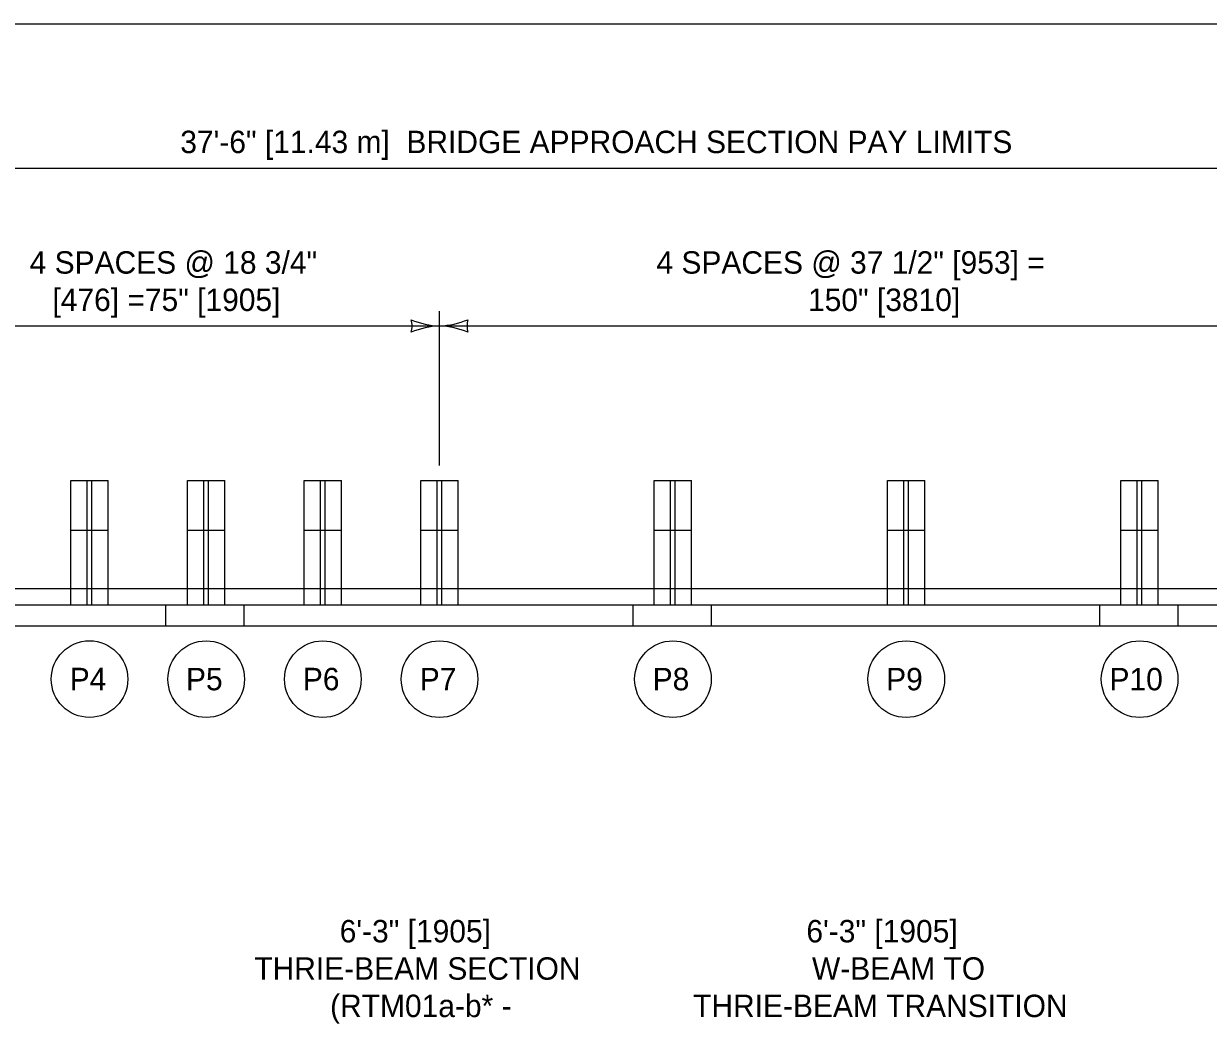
# Model space of a CAD drawing. Extents: x 49991 to 50160, y 49948 to 50051.
# Drawn here: x 50002.708 to 50005.881, y 49996.312 to 49998.999 of the extents above; entities that cross this region are included whole.
import ezdxf

# ---------------------------------------------------------------- set-up
doc = ezdxf.new("R2010")
doc.units = 0
for name, color, linetype in [('Level 1', 7, 'Continuous'), ('Level 2', 7, 'Continuous'), ('Level 3', 7, 'Continuous'), ('Level 4', 7, 'Continuous')]:
    doc.layers.add(name, color=color, linetype=linetype)

msp = doc.modelspace()

# ---------------------------------------------------------------- linework, layer by layer
at = {"layer": 'Level 1'}
for p, q in [((50002.8341, 49997.6431), (50002.8341, 49997.7764)), ((50002.8341, 49997.7764), (50002.9341, 49997.7764)), ((50002.9341, 49997.6431), (50002.9341, 49997.7764)), ((50003.1466, 49997.6431), (50003.1466, 49997.7764)), ((50003.1466, 49997.7764), (50003.2466, 49997.7764)), ((50003.2466, 49997.6431), (50003.2466, 49997.7764)), ((50003.4591, 49997.6431), (50003.4591, 49997.7764)), ((50003.4591, 49997.7764), (50003.5591, 49997.7764)), ((50003.5591, 49997.6431), (50003.5591, 49997.7764)), ((50003.7716, 49997.6431), (50003.7716, 49997.7764)), ((50003.7716, 49997.7764), (50003.8716, 49997.7764)), ((50003.8716, 49997.6431), (50003.8716, 49997.7764)), ((50004.3966, 49997.643), (50004.3966, 49997.7764)), ((50004.3966, 49997.7764), (50004.4966, 49997.7764)), ((50004.4966, 49997.643), (50004.4966, 49997.7764)), ((50005.0216, 49997.643), (50005.0216, 49997.7764)), ((50005.0216, 49997.7764), (50005.1216, 49997.7763)), ((50005.1216, 49997.643), (50005.1216, 49997.7763)), ((50005.6466, 49997.643), (50005.6466, 49997.7763)), ((50005.6466, 49997.7763), (50005.7466, 49997.7763)), ((50005.7466, 49997.643), (50005.7466, 49997.7763)), ((50002.8341, 49997.4431), (50002.8341, 49997.6431)), ((50002.8341, 49997.6431), (50002.9341, 49997.6431)), ((50002.8341, 49997.6431), (50002.9341, 49997.6431)), ((50002.9341, 49997.4431), (50002.9341, 49997.6431)), ((50003.1466, 49997.4431), (50003.1466, 49997.6431)), ((50003.1466, 49997.6431), (50003.2466, 49997.6431)), ((50003.1466, 49997.6431), (50003.2466, 49997.6431)), ((50003.2466, 49997.4431), (50003.2466, 49997.6431)), ((50003.4591, 49997.4431), (50003.4591, 49997.6431)), ((50003.4591, 49997.6431), (50003.5591, 49997.6431)), ((50003.4591, 49997.6431), (50003.5591, 49997.6431)), ((50003.5591, 49997.4431), (50003.5591, 49997.6431)), ((50003.7716, 49997.4431), (50003.7716, 49997.6431)), ((50003.7716, 49997.6431), (50003.8716, 49997.6431)), ((50003.7716, 49997.6431), (50003.8716, 49997.6431)), ((50003.8716, 49997.4431), (50003.8716, 49997.6431)), ((50004.3966, 49997.443), (50004.3966, 49997.643)), ((50004.3966, 49997.643), (50004.4966, 49997.643)), ((50004.3966, 49997.643), (50004.4966, 49997.643)), ((50004.4966, 49997.443), (50004.4966, 49997.643)), ((50005.0216, 49997.443), (50005.0216, 49997.643)), ((50005.0216, 49997.643), (50005.1216, 49997.643)), ((50005.0216, 49997.643), (50005.1216, 49997.643)), ((50005.1216, 49997.443), (50005.1216, 49997.643)), ((50005.6466, 49997.443), (50005.6466, 49997.643)), ((50005.6466, 49997.643), (50005.7466, 49997.643)), ((50005.6466, 49997.643), (50005.7466, 49997.643)), ((50005.7466, 49997.443), (50005.7466, 49997.643)), ((50002.6216, 49997.4869), (50002.8341, 49997.4869)), ((50002.9341, 49997.4869), (50003.1466, 49997.4869)), ((50003.2466, 49997.4869), (50003.4591, 49997.4869)), ((50003.5591, 49997.4869), (50003.7716, 49997.4869)), ((50003.8716, 49997.4869), (50004.3966, 49997.4869)), ((50004.4966, 49997.4869), (50005.0216, 49997.4869)), ((50005.1216, 49997.4869), (50005.6466, 49997.4869)), ((50005.7466, 49997.4869), (50006.2716, 49997.4869)), ((49999.8072, 49997.4432), (50011.6716, 49997.4427)), ((50002.8341, 49997.4431), (50002.9341, 49997.4431)), ((50003.0886, 49997.3869), (50003.0886, 49997.4431)), ((50003.1466, 49997.4431), (50003.2466, 49997.4431)), ((50003.4591, 49997.4431), (50003.5591, 49997.4431)), ((50003.7716, 49997.4431), (50003.8716, 49997.4431)), ((50004.3397, 49997.3868), (50004.3397, 49997.443)), ((50004.3966, 49997.443), (50004.4966, 49997.443)), ((50005.0216, 49997.443), (50005.1216, 49997.443)), ((50005.5897, 49997.3868), (50005.5897, 49997.443)), ((50005.6466, 49997.443), (50005.7466, 49997.443)), ((49999.8072, 49997.387), (50011.6716, 49997.3865))]:
    msp.add_line(p, q, dxfattribs=at)
msp.add_lwpolyline([(49999.3835, 49998.9992), (50016.7501, 49998.9992), (50016.7501, 49987.7988), (49999.3835, 49987.7988)], close=True, dxfattribs=at)
at = {"layer": 'Level 2'}
for centre in [(50002.8841, 49997.2443), (50003.1966, 49997.2442), (50003.509, 49997.2442), (50003.8215, 49997.2442), (50004.4466, 49997.2442), (50005.0715, 49997.2441), (50005.6966, 49997.2441)]:
    msp.add_circle(centre, 0.1026, dxfattribs=at)
at = {"layer": 'Level 3'}
for p, q in [((50000.679, 49998.6127), (50008.1966, 49998.6127)), ((50003.8216, 49997.8164), (50003.8216, 49998.2299)), ((50002.5716, 49998.1899), (50003.8216, 49998.1899)), ((50003.8216, 49998.1899), (50006.3216, 49998.1899))]:
    msp.add_line(p, q, dxfattribs=at)
for centre, radius, start, end in [((50003.8308, 49998.412), 0.2223, 247.456, 267.6395), ((50003.6934, 49998.1899), 0.0548, 342.1388, 17.8612), ((50003.8331, 49997.9572), 0.233, 92.8273, 112.0772), ((50003.8102, 49998.4226), 0.233, 272.8273, 292.0772), ((50003.8125, 49997.9678), 0.2223, 67.456, 87.6395), ((50003.9499, 49998.1899), 0.0548, 162.1388, 197.8612)]:
    msp.add_arc(centre, radius, start, end, dxfattribs=at)
at = {"layer": 'Level 4'}
for p, q in [((50002.8779, 49997.6431), (50002.8779, 49997.7764)), ((50002.8904, 49997.6431), (50002.8904, 49997.7764)), ((50003.1904, 49997.6431), (50003.1904, 49997.7764)), ((50003.2029, 49997.6431), (50003.2029, 49997.7764)), ((50003.5029, 49997.6431), (50003.5029, 49997.7764)), ((50003.5154, 49997.6431), (50003.5154, 49997.7764)), ((50003.8154, 49997.6431), (50003.8154, 49997.7764)), ((50003.8279, 49997.6431), (50003.8279, 49997.7764)), ((50004.4404, 49997.643), (50004.4404, 49997.7764)), ((50004.4529, 49997.643), (50004.4529, 49997.7764)), ((50005.0654, 49997.643), (50005.0654, 49997.7763)), ((50005.0779, 49997.643), (50005.0779, 49997.7763)), ((50005.6904, 49997.643), (50005.6904, 49997.7763)), ((50005.7029, 49997.643), (50005.7029, 49997.7763)), ((50002.8779, 49997.4431), (50002.8779, 49997.6431)), ((50002.8904, 49997.4431), (50002.8904, 49997.6431)), ((50003.1904, 49997.4431), (50003.1904, 49997.6431)), ((50003.2029, 49997.4431), (50003.2029, 49997.6431)), ((50003.5029, 49997.4431), (50003.5029, 49997.6431)), ((50003.5154, 49997.4431), (50003.5154, 49997.6431)), ((50003.8154, 49997.4431), (50003.8154, 49997.6431)), ((50003.8279, 49997.4431), (50003.8279, 49997.6431)), ((50004.4404, 49997.443), (50004.4404, 49997.643)), ((50004.4529, 49997.443), (50004.4529, 49997.643)), ((50005.0654, 49997.443), (50005.0654, 49997.643)), ((50005.0779, 49997.443), (50005.0779, 49997.643)), ((50005.6904, 49997.443), (50005.6904, 49997.643)), ((50005.7029, 49997.443), (50005.7029, 49997.643)), ((50002.8341, 49997.4869), (50002.9341, 49997.4869)), ((50003.1466, 49997.4869), (50003.2466, 49997.4869)), ((50003.4591, 49997.4869), (50003.5591, 49997.4869)), ((50003.7716, 49997.4869), (50003.8716, 49997.4869)), ((50004.3966, 49997.4869), (50004.4966, 49997.4869)), ((50005.0216, 49997.4869), (50005.1216, 49997.4869)), ((50005.6466, 49997.4869), (50005.7466, 49997.4869)), ((50003.2985, 49997.3868), (50003.2985, 49997.4431)), ((50004.5497, 49997.3868), (50004.5497, 49997.443)), ((50005.7997, 49997.3868), (50005.7997, 49997.443))]:
    msp.add_line(p, q, dxfattribs=at)

# ---------------------------------------------------------------- texts
at = {"layer": 'Level 2'}
for s, p in [('37\'-6" [11.43 m]  BRIDGE APPROACH SECTION PAY LIMITS', (50003.1271, 49998.6527)), ('4 SPACES @ 18 3/4"', (50002.7237, 49998.3299)), ('4 SPACES @ 37 1/2" [953] =', (50004.4025, 49998.3299)), (' [476] =75" [1905]', (50002.7624, 49998.2299)), ('150" [3810]', (50004.8084, 49998.2299)), ('P4', (50002.831, 49997.2145)), ('P5', (50003.1424, 49997.2144)), ('P6', (50003.4554, 49997.2145)), ('P7', (50003.7685, 49997.2144)), ('P8', (50004.3924, 49997.2144)), ('P9', (50005.0177, 49997.2143)), ('P10', (50005.616, 49997.2143)), ('6\'-3" [1905] ', (50003.5541, 49996.5394)), ('6\'-3" [1905] ', (50004.8041, 49996.5394)), ('THRIE-BEAM SECTION', (50003.3254, 49996.4394)), ('W-BEAM TO', (50004.8191, 49996.4394)), ('(RTM01a-b* -', (50003.5284, 49996.3394)), ('THRIE-BEAM TRANSITION', (50004.5007, 49996.3394))]:
    msp.add_text(s, height=0.06, dxfattribs=at).set_placement(p)

doc.saveas('drawing.dxf')
